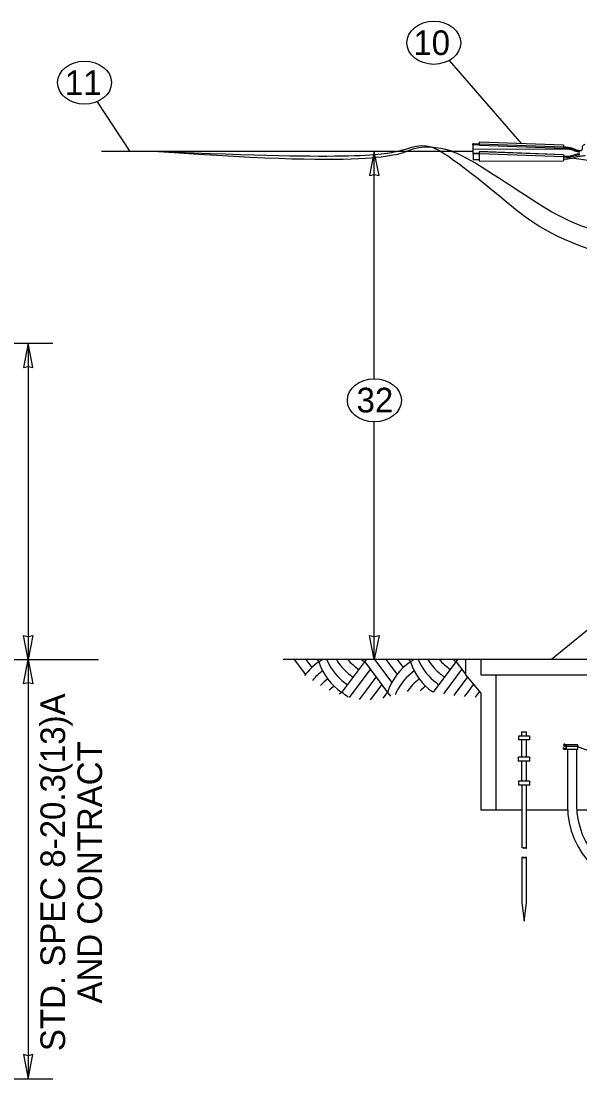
# Model space of a CAD drawing. Extents: x 99862 to 104211, y 98939 to 102076.
# Drawn here: x 101312 to 101675, y 100738 to 101423 of the extents above; entities that cross this region are included whole.
import ezdxf

# ---------------------------------------------------------------- set-up
doc = ezdxf.new("R2010")
doc.units = 0
for name, color, linetype in [('Level 12', 7, 'Continuous'), ('Level 13', 7, 'Continuous'), ('Level 14', 7, 'Continuous'), ('Level 15', 7, 'Continuous'), ('Level 16', 7, 'Continuous'), ('Level 20', 7, 'Continuous'), ('Level 7', 7, 'Continuous')]:
    doc.layers.add(name, color=color, linetype=linetype)

msp = doc.modelspace()

# ---------------------------------------------------------------- linework, layer by layer
at = {"layer": 'Level 12'}
for p, q in [((101584.53, 101338.96), (101364.48, 101338.96)), ((101605.46, 101338.96), (101584.53, 101338.96))]:
    msp.add_line(p, q, dxfattribs=at)
msp.add_open_spline([(101664.3, 101335.46), (101718.51, 101328.04), (101761.77, 101316.71), (101778.05, 101311.49), (101811.01, 101300.81), (101871.2, 101304.04)], degree=3, dxfattribs=at)
at = {"layer": 'Level 13'}
for p, q in [((101605.46, 101343.21), (101605.46, 101343.74)), ((101605.46, 101343.21), (101605.46, 101340.1)), ((101664.65, 101340.41), (101605.46, 101340.1)), ((101605.46, 101340.1), (101605.54, 101333.68)), ((101664.64, 101341.66), (101664.64, 101341.65)), ((101671.41, 101339.79), (101670.89, 101339.97)), ((101670.89, 101339.51), (101671.41, 101339.35)), ((101671.21, 101340.44), (101671.73, 101340.26)), ((101674.84, 101338.89), (101674.84, 101338.89)), ((101670.93, 101336.52), (101671.45, 101336.67)), ((101671.78, 101336.17), (101671.26, 101336.03)), ((101253.2, 101009.51), (101362.51, 101009.51)), ((101600.61, 101009.51), (101482.36, 101009.51)), ((101489.62, 101009.51), (101496.83, 100999.89)), ((101497.04, 101009.51), (101500.91, 101004.35)), ((101504.47, 101009.51), (101505.56, 101008.05)), ((101535.26, 101008.05), (101536.36, 101009.51)), ((101541.59, 101009.51), (101552.78, 100994.58)), ((101549.01, 101009.51), (101556.23, 100999.89)), ((101556.44, 101009.51), (101560.31, 101004.35)), ((101563.86, 101009.51), (101564.96, 101008.05)), ((101594.66, 101008.05), (101595.76, 101009.51)), ((101520.41, 100988.25), (101535.26, 101008.05)), ((101527.84, 100988.25), (101538.97, 101003.1)), ((101535.26, 101008.05), (101550.11, 100988.25)), ((101579.96, 100988.45), (101594.66, 101008.05)), ((101587.23, 100988.25), (101598.37, 101003.1)), ((101594.66, 101008.05), (101600.61, 101000.1)), ((101535.26, 100988.25), (101542.69, 100998.15)), ((101594.66, 100988.25), (101601.94, 100997.96)), ((101542.69, 100988.25), (101546.4, 100993.2)), ((101602.08, 100988.25), (101605.85, 100993.27)), ((101607.15, 100985.11), (101609.76, 100988.58)), ((101525.32, 100984.89), (101527.84, 100988.25)), ((101531.81, 100983.65), (101535.26, 100988.25)), ((101539.03, 100983.37), (101542.69, 100988.25)), ((101547.34, 100984.56), (101550.11, 100988.25)), ((101550.11, 100988.25), (101551.95, 100985.79)), ((101586.59, 100987.39), (101587.23, 100988.25)), ((101593.22, 100986.32), (101594.66, 100988.25)), ((101600.02, 100985.49), (101602.08, 100988.25))]:
    msp.add_line(p, q, dxfattribs=at)
for centre, start, end in [((101484.6, 101039.23), 303.90361, 307.71981), ((101545.09, 101024.38), 203.31888, 228.95992), ((101548.8, 101029.33), 211.84137, 220.94161), ((101552.51, 101034.28), 221.2458, 236.09639), ((101556.22, 101039.23), 232.28019, 236.09639), ((101544, 101039.23), 303.90361, 307.71981), ((101604.48, 101024.38), 203.31888, 228.95992), ((101608.19, 101029.33), 211.84137, 220.94161), ((101611.91, 101034.28), 221.2458, 236.09639), ((101615.62, 101039.23), 232.28019, 236.09639), ((101526.52, 100976.86), 123.90361, 143.60186), ((101530.24, 100971.91), 126.30625, 140.35576), ((101541.37, 101019.44), 197.6434, 236.09639), ((101548.8, 101029.33), 220.94154, 236.09639), ((101585.92, 100976.86), 123.90361, 162.3566), ((101589.63, 100971.91), 126.30625, 154.2266), ((101600.77, 101019.44), 197.6434, 235.31964), ((101608.19, 101029.33), 220.94154, 236.09639), ((101533.95, 100966.96), 127.1006, 136.6781), ((101545.08, 101024.38), 228.95986, 236.09639), ((101593.34, 100966.96), 127.1006, 144.5432), ((101604.48, 101024.38), 228.95986, 236.09639), ((101537.66, 100962.01), 126.331, 132.38675), ((101597.06, 100962.01), 126.331, 133.41416), ((101541.37, 100957.06), 123.90361, 127.12691), ((101499.45, 100957.06), 48.30354, 56.09634), ((101589.63, 100971.91), 154.22654, 156.73364)]:
    msp.add_arc(centre, 37.58, start, end, dxfattribs=at)
for centre, major_axis, ratio, start_param, end_param in [((101664.76, 101331.03), (14.82, -1.11), 0.677735, 1.613936, 1.6292), ((101664.76, 101330.31), (14.84, 0), 0.680094, 1.145355, 1.578471), ((101664.76, 101331.03), (14.82, -1.11), 0.677735, 1.196076, 1.613936), ((101664.76, 101331.03), (15.61, -1.17), 0.677735, 1.196076, 1.310272), ((101678.18, 101349.68), (-16.39, 1.23), 0.677735, 1.196076, 1.416311), ((101678.18, 101349.51), (16.41, 0), 0.680094, 4.286948, 4.507182), ((101678.18, 101349.68), (-15.6, 1.17), 0.677735, 1.196076, 1.405485), ((101664.59, 101345.9), (-14.82, 1.11), 0.677735, 1.629191, 2.062307), ((101664.59, 101345.9), (-15.6, 1.17), 0.677735, 1.948147, 2.062307), ((101678.45, 101326.3), (16.39, -1.23), 0.677735, 1.842068, 2.062308), ((101678.45, 101326.3), (15.6, -1.17), 0.677735, 1.852892, 2.062307)]:
    msp.add_ellipse(centre, major_axis=major_axis, ratio=ratio, start_param=start_param, end_param=end_param, dxfattribs=at)
for points, degree in [([(101609.67, 101343.59), (101607.56, 101343.66), (101605.46, 101343.74)], 2), ([(101609.67, 101343.06), (101608.27, 101343.11), (101606.87, 101343.16), (101605.46, 101343.21)], 2), ([(101664.64, 101341.65), (101664.43, 101341.66), (101664.23, 101341.67)], 2), ([(101664.65, 101341.12), (101664.51, 101341.13), (101664.37, 101341.13), (101664.23, 101341.14)], 2), ([(101664.89, 101341.65), (101664.76, 101341.65), (101664.64, 101341.65)], 2), ([(101669.55, 101340.95), (101668.79, 101341.14), (101668.03, 101341.3), (101666.47, 101341.53), (101665.68, 101341.61), (101664.89, 101341.65)], 3), ([(101674.83, 101339.44), (101675.14, 101339.38), (101675.45, 101339.39), (101675.99, 101339.57), (101676.21, 101339.73), (101676.41, 101340.03), (101676.45, 101340.13), (101676.49, 101340.36), (101676.48, 101340.48), (101676.48, 101340.83), (101676.48, 101341.06), (101676.48, 101341.41), (101676.48, 101341.53), (101676.5, 101341.75), (101676.52, 101341.87), (101676.59, 101342.09), (101676.64, 101342.2), (101676.76, 101342.41), (101676.83, 101342.51), (101677.07, 101342.8), (101677.27, 101342.98), (101677.74, 101343.28), (101678.01, 101343.4), (101678.3, 101343.51)], 3), ([(101605.52, 101337.89), (101606.93, 101337.84), (101608.33, 101337.79), (101609.73, 101337.74)], 2), ([(101609.74, 101337.21), (101607.63, 101337.29), (101605.53, 101337.36)], 2), ([(101605.53, 101333.68), (101607.63, 101333.69), (101609.74, 101333.7)], 2), ([(101664.29, 101335.83), (101664.43, 101335.82), (101664.57, 101335.82), (101664.71, 101335.81)], 2), ([(101664.71, 101335.28), (101664.5, 101335.29), (101664.3, 101335.29)], 2), ([(101664.3, 101333.99), (101664.5, 101333.99), (101664.71, 101333.99)], 2), ([(101669.61, 101335.64), (101668.82, 101335.49), (101668.01, 101335.39), (101666.37, 101335.26), (101665.54, 101335.25), (101664.71, 101335.28)], 3), ([(101664.71, 101333.99), (101665.85, 101333.99), (101666.96, 101334.08), (101669.15, 101334.42), (101670.23, 101334.67), (101671.26, 101335)], 3), ([(101671.26, 101335), (101672.81, 101335.5), (101673.87, 101335.75), (101676.06, 101336.09), (101677.19, 101336.18), (101678.33, 101336.19)], 3)]:
    msp.add_open_spline(points, degree=degree, dxfattribs=at)
at = {"layer": 'Level 14'}
for p, q in [((101664.21, 101342.9), (101609.66, 101344.86)), ((101609.67, 101343.69), (101609.66, 101344.86)), ((101664.22, 101341.73), (101609.67, 101343.69)), ((101609.68, 101342.69), (101609.68, 101342.81)), ((101664.23, 101340.73), (101609.68, 101342.69)), ((101664.28, 101336.79), (101609.73, 101338.76)), ((101609.74, 101337.42), (101609.73, 101338.76)), ((101664.28, 101336.63), (101609.73, 101338.59)), ((101664.21, 101342.9), (101664.22, 101341.73)), ((101664.23, 101340.84), (101664.23, 101340.73)), ((101609.74, 101332.6), (101609.74, 101337.42)), ((101664.3, 101335.46), (101609.74, 101337.42)), ((101609.74, 101332.6), (101664.3, 101332.89)), ((101664.28, 101336.63), (101664.3, 101335.46)), ((101664.3, 101335.46), (101664.3, 101332.89))]:
    msp.add_line(p, q, dxfattribs=at)
for centre, start_param, end_param in [((101609.67, 101343.23), 3.965269, 5.536065), ((101664.22, 101341.27), 3.965269, 5.536065), ((101664.28, 101336.17), 5.536065, 6.283186)]:
    msp.add_ellipse(centre, major_axis=(-0.003, 0.626), ratio=0.005626, start_param=start_param, end_param=end_param, dxfattribs=at)
at = {"layer": 'Level 15'}
for p, q in [((101590.08, 101397.85), (101636.94, 101343.88)), ((101361.71, 101371.13), (101382.97, 101338.96)), ((101541.49, 101191.56), (101541.49, 101338.96)), ((101014.48, 101214.51), (101332.92, 101214.51)), ((101316.92, 101214.51), (101316.92, 101009.51)), ((101541.49, 101009.51), (101541.49, 101163.57)), ((101713.46, 101056.22), (101656.4, 101009.51)), ((101316.92, 101009.51), (101316.92, 100737.75)), ((101743.01, 100927.09), (101673.55, 100952.88)), ((101051.67, 100737.75), (101332.92, 100737.75))]:
    msp.add_line(p, q, dxfattribs=at)
for points in [[(101541.49, 101338.96), (101538.4, 101323.23), (101541.49, 101323.96), (101544.57, 101323.23)], [(101316.92, 101214.51), (101313.84, 101198.78), (101316.92, 101199.51), (101320.01, 101198.78)], [(101316.92, 101009.51), (101313.84, 101025.23), (101316.92, 101024.51), (101320.01, 101025.23)], [(101541.49, 101009.51), (101538.4, 101025.23), (101541.49, 101024.51), (101544.57, 101025.23)], [(101316.92, 101009.51), (101320.01, 100993.78), (101316.92, 100994.51), (101313.84, 100993.78)], [(101316.92, 100737.75), (101320.01, 100753.47), (101316.92, 100752.74), (101313.84, 100753.47)]]:
    msp.add_lwpolyline(points, close=True, dxfattribs=at)
at = {"layer": 'Level 16'}
for points in [[(101401.49, 101338.96), (101531.17, 101333.34), (101565, 101340.1), (101574.2, 101344.95), (101584.53, 101339.05)], [(101401.45, 101338.96), (101548.56, 101328.14), (101565.04, 101346.63), (101587.87, 101340.64), (101592.02, 101339.03)], [(101584.53, 101338.96), (101590.2, 101335.72), (101616.28, 101316.78), (101685.63, 101256.57), (101850, 101257.11)], [(101592.05, 101338.93), (101607.71, 101332.86), (101648.17, 101301.81), (101704.43, 101273.82), (101851.09, 101279.6)]]:
    msp.add_open_spline(points, degree=3, dxfattribs=at)
at = {"layer": 'Level 20'}
for centre in [(101580.09, 101409.34), (101353.53, 101383.51), (101541.56, 101177.56)]:
    msp.add_ellipse(centre, major_axis=(-17.5, 0), ratio=0.8, dxfattribs=at)
at = {"layer": 'Level 7'}
for p, q in [((101610.54, 101009.51), (101600.61, 101009.51)), ((101600.61, 101009.51), (101600.61, 100999.56)), ((101705.83, 101009.51), (101610.54, 101009.51)), ((101610.54, 101009.51), (101610.54, 100999.56)), ((101600.61, 100999.56), (101610.54, 100987.65)), ((101610.54, 100999.56), (101705.83, 100999.56)), ((101620.46, 100912.17), (101620.46, 100999.56)), ((101610.54, 100987.65), (101610.54, 100912.17)), ((101637.15, 100962.6), (101640.33, 100962.6)), ((101637.15, 100960.18), (101637.15, 100962.6)), ((101640.33, 100960.18), (101640.33, 100962.6)), ((101637.15, 100946.42), (101637.15, 100957.45)), ((101640.33, 100946.42), (101640.33, 100957.45)), ((101665.96, 100953.48), (101673.55, 100953.48)), ((101666.8, 100951.48), (101666.8, 100915.07)), ((101672.71, 100951.48), (101672.71, 100915.23)), ((101637.15, 100930.82), (101637.15, 100943.69)), ((101640.33, 100930.82), (101640.33, 100943.69)), ((101637.15, 100928.06), (101637.15, 100887.55)), ((101640.33, 100887.55), (101640.34, 100928.06)), ((101610.54, 100912.17), (101620.46, 100912.17)), ((101620.46, 100912.17), (101637.15, 100912.17)), ((101640.34, 100912.17), (101666.8, 100912.17)), ((101672.71, 100912.17), (101695.91, 100912.17)), ((101637.15, 100887.55), (101637.54, 100887.95)), ((101637.54, 100887.95), (101638.31, 100887.15)), ((101638.31, 100887.15), (101638.74, 100887.95)), ((101638.74, 100887.95), (101639.19, 100887.15)), ((101639.19, 100887.15), (101639.96, 100887.95)), ((101639.96, 100887.95), (101639.96, 100887.15)), ((101639.96, 100887.15), (101640.33, 100887.55)), ((101637.15, 100881.17), (101637.54, 100881.57)), ((101637.15, 100881.17), (101637.15, 100851.89)), ((101637.54, 100881.57), (101638.31, 100880.77)), ((101638.31, 100880.77), (101638.74, 100881.57)), ((101638.74, 100881.57), (101639.19, 100880.77)), ((101639.19, 100880.77), (101639.96, 100881.57)), ((101639.96, 100881.57), (101639.96, 100880.77)), ((101639.96, 100880.77), (101640.33, 100881.17)), ((101640.33, 100851.89), (101640.33, 100881.17)), ((101637.15, 100851.89), (101638.74, 100839.95)), ((101638.74, 100839.95), (101640.33, 100851.89))]:
    msp.add_line(p, q, dxfattribs=at)
for points in [[(101635.18, 100960.18), (101642.29, 100960.18), (101642.29, 100957.45), (101635.18, 100957.45)], [(101664.16, 100952.54), (101664.16, 100951.48), (101665.96, 100951.48), (101665.96, 100954.28), (101664.76, 100954.28), (101664.76, 100954.08), (101665.76, 100954.08), (101665.76, 100951.68), (101664.35, 100951.68), (101664.35, 100952.54)], [(101664.16, 100954.08), (101664.62, 100954.08), (101664.62, 100954.28), (101664.16, 100954.28)], [(101673.55, 100954.28), (101665.96, 100954.28), (101665.96, 100951.48), (101673.55, 100951.48)], [(101635.13, 100946.42), (101642.21, 100946.42), (101642.21, 100943.69), (101635.13, 100943.69)], [(101635.18, 100930.82), (101642.29, 100930.82), (101642.29, 100928.06), (101635.18, 100928.06)]]:
    msp.add_lwpolyline(points, close=True, dxfattribs=at)
for points in [[(101665.2, 100954.28), (101665.2, 100954.65), (101664.43, 100954.65), (101664.43, 100954.28)], [(101664.43, 100954.08), (101664.43, 100953.33), (101665.2, 100953.33), (101665.2, 100954.08)]]:
    msp.add_lwpolyline(points, dxfattribs=at)
for centre, radius in [((101722.55, 100915.07), 55.75), ((101722.71, 100915.23), 50)]:
    msp.add_arc(centre, radius, 180, 270, dxfattribs=at)

# ---------------------------------------------------------------- texts
at = {"layer": 'Level 20'}
for s, p in [('10', (101566.84, 101401.35)), ('11', (101340.81, 101375.51)), ('32', (101530.01, 101169.7))]:
    msp.add_text(s, height=16, dxfattribs=at).set_placement(p)
for s, p in [('STD. SPEC 8-20.3(13)A', (101340.92, 100755.72)), ('AND CONTRACT', (101364.92, 100786.55))]:
    msp.add_text(s, height=16, rotation=90, dxfattribs=at).set_placement(p)

doc.saveas('drawing.dxf')
